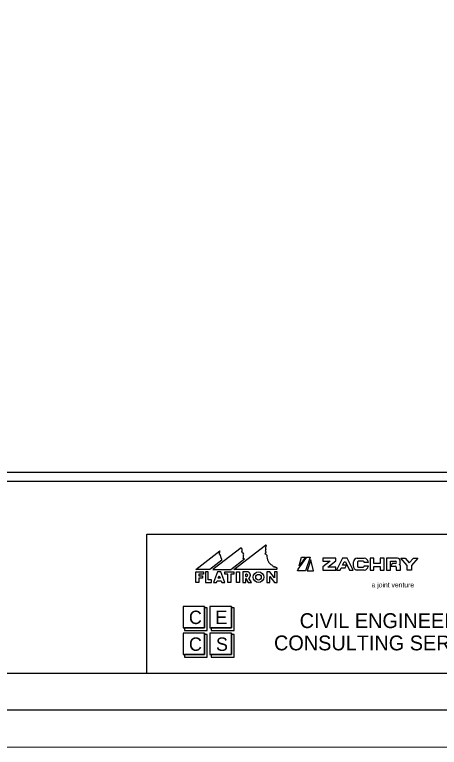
# Model space of a CAD drawing. Extents: x -2251 to 10196, y -13470 to 1199.
# Drawn here: x 8724.8 to 9010.7, y -4450.7 to -3957.3 of the extents above; entities that cross this region are included whole.
import ezdxf

# ---------------------------------------------------------------- set-up
doc = ezdxf.new("R2010")
doc.units = 0
for name, color, linetype in [('Level 3', 7, 'Continuous'), ('RD_SHT_Bndy', 7, 'Continuous'), ('RD_SHT_Iplotshp', 7, 'Continuous'), ('RD_SHT_Logo', 7, 'Continuous'), ('RD_SHT_TX', 7, 'Continuous'), ('RD_TX_RoadID', 7, 'Continuous')]:
    doc.layers.add(name, color=color, linetype=linetype)

msp = doc.modelspace()

# ---------------------------------------------------------------- linework, layer by layer
at = {"layer": 'Level 3'}
msp.add_line((8965.07, -4363.99), (8965.07, -4363.99), dxfattribs=at)
msp.add_line((8965.07, -4363.99), (8965.07, -4363.99), dxfattribs=at)
msp.add_line((8965.07, -4363.99), (8965.07, -4363.99), dxfattribs=at)
msp.add_line((8965.07, -4363.99), (8965.07, -4363.99), dxfattribs=at)
at = {"layer": 'RD_SHT_Bndy'}
for p, q in [((7603.1, -4400.65), (9278.1, -4400.65)), ((9291.65, -4425.65), (7531.65, -4425.65)), ((9291.6, -4450.7), (7531.6, -4450.65))]:
    msp.add_line(p, q, dxfattribs=at)
msp.add_lwpolyline([(7653.4, -3401.26), (9231.08, -3401.26), (9231.08, -4265.57), (7653.4, -4265.57)], close=True, dxfattribs=at)
at = {"layer": 'RD_SHT_Iplotshp'}
msp.add_lwpolyline([(7496.65, -3325.65), (9296.65, -3325.65), (9296.65, -4425.65), (7496.65, -4425.65)], close=True, dxfattribs=at)
at = {"layer": 'RD_SHT_Logo'}
for p, q in [((8877.35, -4316.27), (8858.31, -4330.86)), ((8872.32, -4330.86), (8893.74, -4314.44)), ((8846.7, -4330.86), (8862.98, -4318.38)), ((8864.27, -4324.74), (8856.29, -4330.86)), ((8870.3, -4330.86), (8879.48, -4323.82)), ((8915.56, -4330.77), (8921.47, -4322.59)), ((8920.48, -4322.59), (8916.24, -4328.47)), ((8916.24, -4328.47), (8917.96, -4322.59)), ((8917.96, -4322.59), (8920.48, -4322.59)), ((8923.82, -4322.59), (8920.68, -4331.76)), ((8921.47, -4322.59), (8923.82, -4322.59)), ((8924.24, -4324.44), (8921.74, -4331.76)), ((8925.99, -4331.76), (8924.24, -4324.44)), ((8940.93, -4323.35), (8932.22, -4323.35)), ((8932.22, -4323.35), (8932.22, -4325.3)), ((8937.2, -4325.3), (8932.22, -4329.24)), ((8932.22, -4325.3), (8937.2, -4325.3)), ((8935.63, -4329.35), (8940.93, -4325.16)), ((8940.93, -4325.16), (8940.93, -4323.35)), ((8945.58, -4323.35), (8941.53, -4331.3)), ((8945.57, -4327.99), (8946.71, -4325.75)), ((8948.58, -4323.35), (8945.58, -4323.35)), ((8946.71, -4325.75), (8947.44, -4325.75)), ((8947.44, -4325.75), (8950.27, -4331.3)), ((8952.63, -4331.3), (8948.58, -4323.35)), ((8952.94, -4328.8), (8952.94, -4325.85)), ((8955.44, -4323.35), (8960.18, -4323.35)), ((8955.64, -4325.8), (8955.64, -4328.85)), ((8959.48, -4325.3), (8956.14, -4325.3)), ((8959.98, -4326.15), (8959.98, -4325.8)), ((8962.68, -4326.15), (8959.98, -4326.15)), ((8962.68, -4325.85), (8962.68, -4326.15)), ((8966.62, -4323.35), (8964.02, -4323.35)), ((8964.02, -4323.35), (8964.02, -4331.3)), ((8966.62, -4326.8), (8966.62, -4323.35)), ((8970.9, -4326.8), (8966.62, -4326.8)), ((8970.9, -4323.35), (8970.9, -4326.8)), ((8973.51, -4323.35), (8970.9, -4323.35)), ((8973.5, -4331.3), (8973.51, -4323.35)), ((8982.43, -4323.35), (8975.13, -4323.35)), ((8975.13, -4323.35), (8975.13, -4331.3)), ((8977.83, -4331.3), (8977.83, -4325.31)), ((8977.83, -4325.31), (8981.07, -4325.31)), ((8979.03, -4326.97), (8978.11, -4328.77)), ((8981.07, -4326.97), (8979.03, -4326.97)), ((8984.43, -4326.36), (8984.43, -4325.35)), ((8984.68, -4323.35), (8987.64, -4323.35)), ((8989.08, -4328.24), (8984.68, -4323.35)), ((8987.64, -4323.35), (8990.48, -4326.51)), ((8990.48, -4326.51), (8993.32, -4323.35)), ((8996.28, -4323.35), (8991.88, -4328.24)), ((8993.32, -4323.35), (8996.28, -4323.35)), ((8856.29, -4330.86), (8846.7, -4330.86)), ((8858.31, -4330.86), (8870.3, -4330.86)), ((8901.19, -4330.86), (8872.32, -4330.86)), ((8915.27, -4331.76), (8915.56, -4330.77)), ((8920.68, -4331.76), (8915.27, -4331.76)), ((8921.74, -4331.76), (8925.99, -4331.76)), ((8932.22, -4329.24), (8932.22, -4331.3)), ((8932.22, -4331.3), (8940.93, -4331.3)), ((8940.93, -4329.35), (8935.63, -4329.35)), ((8940.93, -4331.3), (8940.93, -4329.35)), ((8941.53, -4331.3), (8943.88, -4331.3)), ((8943.88, -4331.3), (8944.65, -4329.79)), ((8944.65, -4329.79), (8947.23, -4329.79)), ((8948.15, -4327.99), (8945.57, -4327.99)), ((8947.23, -4329.79), (8948.15, -4327.99)), ((8950.27, -4331.3), (8952.63, -4331.3)), ((8960.18, -4331.3), (8955.44, -4331.3)), ((8956.14, -4329.35), (8959.48, -4329.35)), ((8959.98, -4328.5), (8962.68, -4328.5)), ((8959.98, -4328.85), (8959.98, -4328.5)), ((8962.68, -4328.5), (8962.68, -4328.8)), ((8964.02, -4331.3), (8966.62, -4331.3)), ((8966.62, -4331.3), (8966.62, -4328.8)), ((8966.62, -4328.8), (8970.9, -4328.8)), ((8970.9, -4328.8), (8970.9, -4331.3)), ((8970.9, -4331.3), (8973.5, -4331.3)), ((8975.13, -4331.3), (8977.83, -4331.3)), ((8978.11, -4328.77), (8981.24, -4328.77)), ((8981.74, -4329.27), (8981.74, -4331.3)), ((8981.74, -4331.3), (8984.54, -4331.3)), ((8983.68, -4327.6), (8983.68, -4327.47)), ((8984.54, -4331.3), (8984.54, -4328.76)), ((8989.08, -4331.3), (8989.08, -4328.24)), ((8991.88, -4331.3), (8989.08, -4331.3)), ((8991.88, -4328.24), (8991.88, -4331.3)), ((8846.72, -4339.7), (8846.72, -4332.5)), ((8846.72, -4332.5), (8851.82, -4332.5)), ((8851.82, -4334.15), (8848.67, -4334.15)), ((8848.67, -4334.15), (8848.67, -4335.21)), ((8848.67, -4335.21), (8851.22, -4335.21)), ((8851.22, -4336.86), (8848.67, -4336.86)), ((8848.67, -4336.86), (8848.67, -4339.7)), ((8851.22, -4335.21), (8851.22, -4336.86)), ((8851.82, -4332.5), (8851.82, -4334.15)), ((8855.12, -4332.5), (8853.17, -4332.5)), ((8853.17, -4332.5), (8853.17, -4339.7)), ((8855.12, -4337.9), (8855.12, -4332.5)), ((8861.42, -4332.5), (8858.65, -4339.71)), ((8863.52, -4332.5), (8861.42, -4332.5)), ((8861.83, -4336.86), (8862.47, -4335.2)), ((8863.1, -4336.86), (8861.83, -4336.86)), ((8862.47, -4335.2), (8863.1, -4336.86)), ((8866.28, -4339.71), (8863.52, -4332.5)), ((8866.22, -4334.15), (8866.22, -4332.5)), ((8866.22, -4332.5), (8872.37, -4332.5)), ((8868.32, -4334.15), (8866.22, -4334.15)), ((8868.32, -4339.71), (8868.32, -4334.15)), ((8872.37, -4334.15), (8870.27, -4334.15)), ((8870.27, -4334.15), (8870.27, -4339.71)), ((8872.37, -4332.5), (8872.37, -4334.15)), ((8874.17, -4339.71), (8874.17, -4332.5)), ((8874.17, -4332.5), (8876.12, -4332.5)), ((8876.12, -4332.5), (8876.12, -4339.71)), ((8881.8, -4332.5), (8878.38, -4332.5)), ((8878.38, -4332.5), (8878.38, -4339.71)), ((8880.33, -4335.66), (8880.33, -4334.01)), ((8880.33, -4339.71), (8880.33, -4337.02)), ((8880.33, -4337.02), (8881.94, -4339.71)), ((8884.16, -4339.71), (8882.43, -4336.82)), ((8896.52, -4332.5), (8894.57, -4332.5)), ((8894.57, -4332.5), (8894.57, -4339.71)), ((8899.67, -4336.53), (8896.52, -4332.5)), ((8896.52, -4339.71), (8896.52, -4335.67)), ((8896.52, -4335.67), (8899.67, -4339.71)), ((8901.62, -4332.5), (8899.67, -4332.5)), ((8899.67, -4332.5), (8899.67, -4336.53)), ((8901.62, -4339.71), (8901.62, -4332.5)), ((8848.67, -4339.7), (8846.72, -4339.7)), ((8853.17, -4339.7), (8857.37, -4339.71)), ((8857.37, -4337.9), (8855.12, -4337.9)), ((8857.37, -4339.71), (8857.37, -4337.9)), ((8858.65, -4339.71), (8860.74, -4339.71)), ((8860.74, -4339.71), (8861.2, -4338.51)), ((8861.2, -4338.51), (8863.74, -4338.51)), ((8863.74, -4338.51), (8864.2, -4339.71)), ((8864.2, -4339.71), (8866.28, -4339.71)), ((8870.27, -4339.71), (8868.32, -4339.71)), ((8876.12, -4339.71), (8874.17, -4339.71)), ((8878.38, -4339.71), (8880.33, -4339.71)), ((8881.94, -4339.71), (8884.16, -4339.71)), ((8894.57, -4339.71), (8896.52, -4339.71)), ((8899.67, -4339.71), (8901.62, -4339.71)), ((8852.67, -4355.79), (8838.28, -4355.79)), ((8838.28, -4355.79), (8838.28, -4370.23)), ((8852.67, -4370.23), (8852.67, -4355.79)), ((8852.67, -4355.79), (8852.67, -4370.23)), ((8854.48, -4356.7), (8852.67, -4356.7)), ((8854.48, -4372.03), (8854.48, -4356.7)), ((8870.67, -4355.79), (8856.27, -4355.79)), ((8856.27, -4355.79), (8856.27, -4370.23)), ((8870.67, -4370.23), (8870.67, -4355.79)), ((8870.67, -4355.79), (8870.67, -4370.23)), ((8872.48, -4356.7), (8870.67, -4356.7)), ((8872.48, -4372.03), (8872.48, -4356.7)), ((8838.28, -4370.23), (8852.67, -4370.23)), ((8852.67, -4370.23), (8839.17, -4370.23)), ((8839.17, -4370.23), (8839.17, -4372.03)), ((8856.27, -4370.23), (8870.67, -4370.23)), ((8870.67, -4370.23), (8857.18, -4370.23)), ((8857.18, -4370.23), (8857.18, -4372.03)), ((8852.67, -4373.84), (8838.28, -4373.84)), ((8838.28, -4373.84), (8838.28, -4388.27)), ((8839.17, -4372.03), (8854.48, -4372.03)), ((8852.67, -4388.27), (8852.67, -4373.84)), ((8852.67, -4373.84), (8852.67, -4388.27)), ((8854.48, -4374.74), (8852.67, -4374.74)), ((8854.48, -4390.07), (8854.48, -4374.74)), ((8870.67, -4373.84), (8856.27, -4373.84)), ((8856.27, -4373.84), (8856.27, -4388.27)), ((8857.18, -4372.03), (8872.48, -4372.03)), ((8870.67, -4388.27), (8870.67, -4373.84)), ((8870.67, -4373.84), (8870.67, -4388.27)), ((8872.48, -4374.74), (8870.67, -4374.74)), ((8872.48, -4390.07), (8872.48, -4374.74)), ((8838.28, -4388.27), (8852.67, -4388.27)), ((8852.67, -4388.27), (8839.17, -4388.27)), ((8839.17, -4388.27), (8839.17, -4390.07)), ((8839.17, -4390.07), (8854.48, -4390.07)), ((8856.27, -4388.27), (8870.67, -4388.27)), ((8870.67, -4388.27), (8857.18, -4388.27)), ((8857.18, -4388.27), (8857.18, -4390.07)), ((8857.18, -4390.07), (8872.48, -4390.07))]:
    msp.add_line(p, q, dxfattribs=at)
for radius in [3.6, 1.9]:
    msp.add_circle((8888.95, -4336.1), radius, dxfattribs=at)
for centre, radius, start, end in [((8875.05, -4318.02), 2.89, 342.0343, 37.2653), ((8893.13, -4317.66), 0.749, 309.4079, 17.0499), ((8897.87, -4316.34), 4.17, 156.4699, 195.3053), ((8893.86, -4314.6), 0.2, 336.4699, 127.4657), ((8866.29, -4320.12), 3.74, 152.2252, 185.8662), ((8862.1, -4321.62), 1.21, 351.6466, 67.1294), ((8864.29, -4321.94), 1, 171.6466, 221.9371), ((8877.99, -4318.97), 0.2, 162.0343, 220.8638), ((8876.86, -4319.95), 1.3, 11.8745, 40.8638), ((8878.32, -4319.64), 0.2, 191.8745, 279.8173), ((8878.44, -4320.33), 0.499, 44.4799, 99.8173), ((8875.8, -4322.18), 3.16, 331.2486, 18.4584), ((8879.5, -4320.72), 0.843, 144.641, 212.5499), ((8878.65, -4320.12), 0.2, 324.641, 44.4799), ((8893.57, -4320.5), 0.2, 133.0036, 262.3069), ((8891.59, -4318.37), 2.7, 313.0036, 343.6807), ((8893.73, -4318.39), 0.2, 129.4079, 246.863), ((8893.31, -4322.44), 1.76, 45.283, 82.3069), ((8893.27, -4319.47), 0.973, 20.4113, 66.863), ((8894.4, -4321.33), 0.2, 353.8329, 45.283), ((8901.36, -4322.08), 6.8, 173.8329, 242.3928), ((8863.11, -4323.01), 0.592, 327.6019, 41.9371), ((8863.3, -4324.33), 1.05, 337.4201, 73.1261), ((8878.92, -4324.44), 0.827, 48.0701, 115.7229), ((8955.44, -4325.85), 2.5, 89.9984, 179.9984), ((8956.14, -4325.8), 0.5, 89.9984, 179.9984), ((8959.48, -4325.8), 0.5, 359.9984, 89.9984), ((8960.18, -4325.85), 2.5, 359.9984, 89.9984), ((8981.07, -4326.14), 0.831, 269.9984, 89.9984), ((8982.43, -4325.35), 2, 359.9984, 89.9984), ((8983.23, -4326.36), 1.2, 291.95, 359.9984), ((8898.12, -4328.28), 0.2, 9.0833, 62.3928), ((8899.35, -4328.09), 1.04, 189.0833, 295.769), ((8899.89, -4329.21), 0.2, 33.7112, 115.769), ((8900.89, -4328.54), 1.01, 213.7112, 268.6299), ((8900.86, -4329.74), 0.2, 78.9712, 88.6299), ((8900.75, -4330.3), 0.767, 320.912, 78.9712), ((8901.19, -4330.66), 0.2, 269.9984, 320.912), ((8955.44, -4328.8), 2.5, 179.9984, 269.9984), ((8956.14, -4328.85), 0.5, 179.9984, 269.9984), ((8959.48, -4328.85), 0.5, 269.9984, 359.9984), ((8960.18, -4328.8), 2.5, 269.9984, 359.9984), ((8981.24, -4329.27), 0.5, 359.9984, 89.9984), ((8983.34, -4328.76), 1.2, 359.9984, 73.7977)]:
    msp.add_arc(centre, radius, start, end, dxfattribs=at)
msp.add_ellipse((8880.33, -4334.83), major_axis=(1.36, 0), ratio=0.609965, start_param=4.712389, end_param=7.853982, dxfattribs=at)
msp.add_open_spline([(8882.43, -4336.82), (8882.51, -4336.76), (8882.59, -4336.7), (8882.81, -4336.49), (8882.95, -4336.34), (8883.13, -4336.07), (8883.19, -4335.97), (8883.29, -4335.77), (8883.34, -4335.66), (8883.41, -4335.44), (8883.44, -4335.32), (8883.47, -4335.08), (8883.48, -4334.96), (8883.48, -4334.71), (8883.47, -4334.59), (8883.44, -4334.35), (8883.41, -4334.23), (8883.34, -4334.01), (8883.29, -4333.9), (8883.19, -4333.7), (8883.13, -4333.6), (8882.95, -4333.33), (8882.81, -4333.18), (8882.52, -4332.91), (8882.37, -4332.8), (8882.08, -4332.63), (8881.94, -4332.56), (8881.8, -4332.5)], degree=3, dxfattribs=at)
at = {"layer": 'RD_SHT_TX'}
for p, q in [((8813.76, -4400.65), (8813.76, -4307.15)), ((8813.76, -4400.65), (8813.76, -4307.15)), ((8813.76, -4307.15), (9278.1, -4307.15))]:
    msp.add_line(p, q, dxfattribs=at)
at = {"layer": 'RD_TX_RoadID'}
msp.add_lwpolyline([(7647.39, -4271.35), (9237.09, -4271.35), (9237.09, -3465.04), (7647.39, -3465.04)], close=True, dxfattribs=at)

# ---------------------------------------------------------------- texts
at = {"layer": 'RD_SHT_Logo'}
msp.add_text('a joint venture', height=3.3, rotation=359.9984, dxfattribs=at).set_placement((8965.08, -4342.93))
for s, height, p in [('C', 9.02, (8842.11, -4367.66)), ('E', 9.02, (8859.9, -4367.66)), ('CIVIL ENGINEERING', 10, (8916.67, -4370.38)), ('C', 9.02, (8842.11, -4385.71)), ('S', 9.02, (8860.32, -4385.71)), ('CONSULTING SERVICES, INC.', 10, (8899.39, -4385.38))]:
    msp.add_text(s, height=height, dxfattribs=at).set_placement(p)

doc.saveas('drawing.dxf')
